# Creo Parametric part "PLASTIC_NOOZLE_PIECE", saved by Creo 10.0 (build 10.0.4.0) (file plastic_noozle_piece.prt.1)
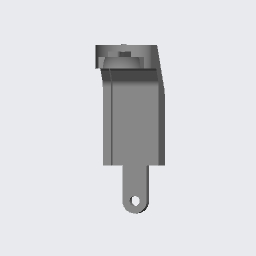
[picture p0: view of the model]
Units: millimeter Kilogram Sec (mmKs); MM, KILOGRAM, SECS

Created from: XX_SOLID_PART_MMKS_NEW_ABS.PRT

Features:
  1. datum plane "RIGHT"
  2. datum plane "TOP"
  3. datum plane "FRONT"
  4. coordinate system
  5. extrusion "Extrude 1"
  6. extruded cut "Extrude 2"
  7. extruded cut "Extrude 3"
  8. extruded cut "Extrude 4"
  9. extruded cut "Extrude 5"
  10. extruded cut "Extrude 6"
  11. extruded cut "Extrude 7"
  12. sketch "Sketch 1"
  13. revolve "Revolve 1"
  14. extrusion "Extrude 8"
  15. extruded cut "Extrude 9"
  16. chamfer "Chamfer 1"
  17. sketch "Sketch 2"
  18. revolve "Revolve 2"
  19. sketch "Sketch 3"
  20. cut
  21. extruded cut "Extrude 10"
  22. sketch "Sketch 4"
  23. extruded cut "Extrude 11"
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
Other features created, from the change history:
  planar section "XSEC0001"
  round "Round 1"
  sketch "Sketch 5"

Surfaces: 46 plane, 22 cylinder, 4 torus, 2 cone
